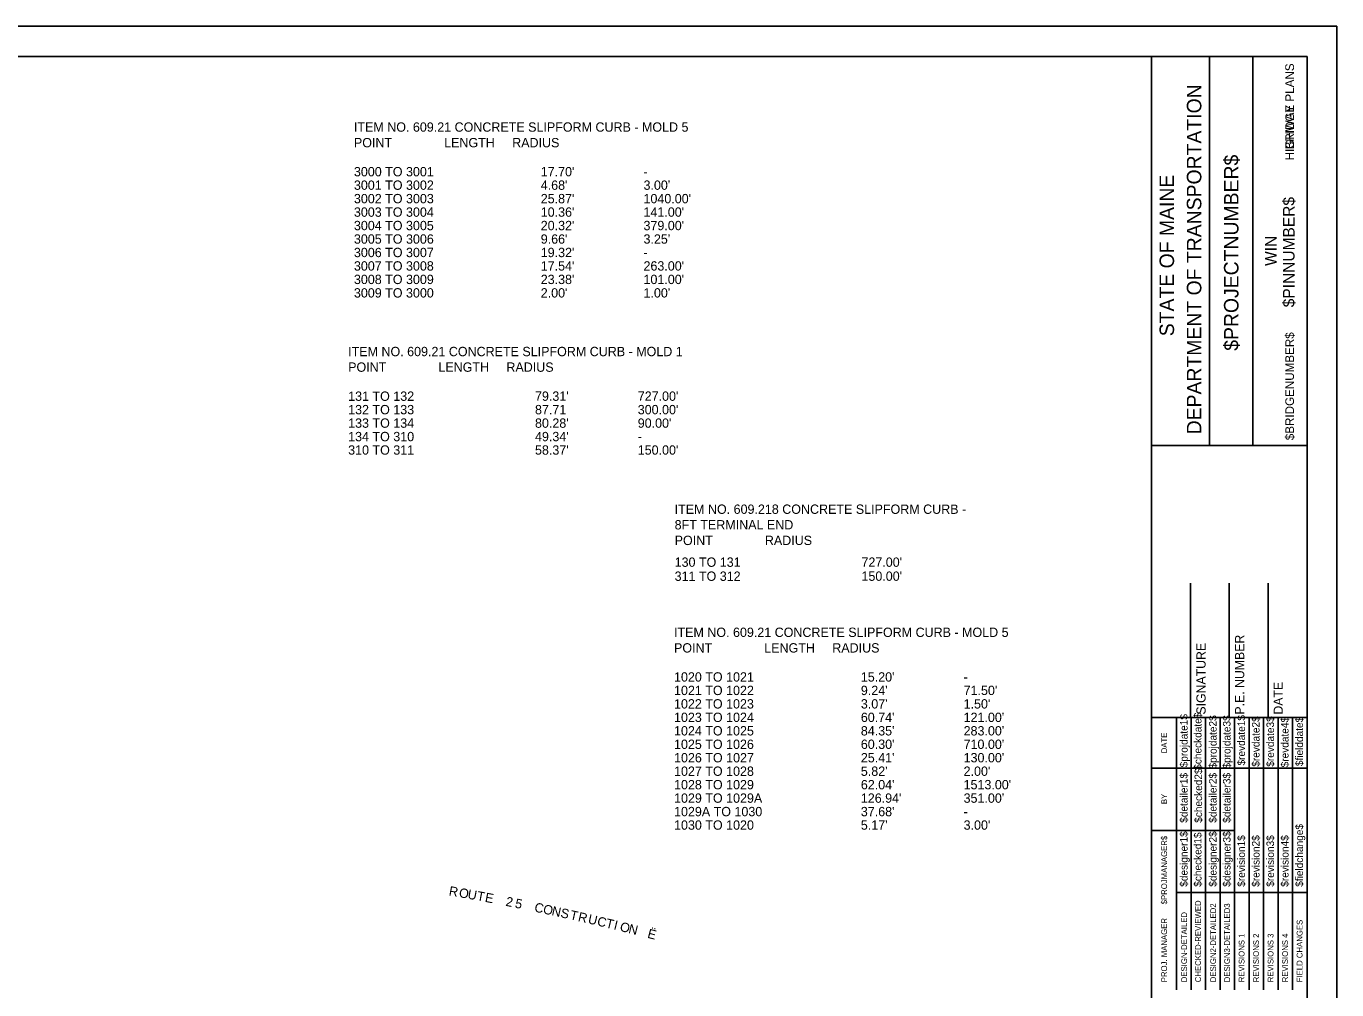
# Model space of a CAD drawing. Extents: x 916257 to 917115, y 329394 to 329944.
# Drawn here: x 916686.1 to 917107, y 329634.2 to 329943.9 of the extents above; entities that cross this region are included whole.
import ezdxf

# ---------------------------------------------------------------- set-up
doc = ezdxf.new("R2010")
doc.units = 0
for name, color, linetype in [('ANNOTATION', 7, 'Continuous'), ('D_Curb_Type1_Lt', 7, 'Continuous'), ('D_Curb_Type_5_Lt', 7, 'Continuous'), ('D_Curb_Type_5_Rt', 7, 'Continuous'), ('D_Roadway_Edge_Pavement', 7, 'Continuous')]:
    doc.layers.add(name, color=color, linetype=linetype)

msp = doc.modelspace()

# ---------------------------------------------------------------- linework, layer by layer
at = {"layer": 'D_Curb_Type1_Lt'}
msp.add_lwpolyline([(916257, 329393.91), (917107, 329393.91), (917107, 329943.91), (916257, 329943.91)], close=True, dxfattribs=at)
at = {"layer": 'D_Roadway_Edge_Pavement'}
for p, q in [((917097.47, 329934.21), (916297.47, 329934.21)), ((917047.47, 329409.22), (917047.47, 329934.22)), ((917066.11, 329809.19), (917066.11, 329934.19)), ((917080.08, 329809.19), (917080.08, 329934.19)), ((917097.47, 329409.22), (917097.47, 329934.22)), ((917047.47, 329809.18), (917097.47, 329809.18)), ((917059.97, 329721.72), (917059.97, 329764.96)), ((917072.47, 329721.72), (917072.47, 329764.96)), ((917084.97, 329721.72), (917084.97, 329764.96)), ((917047.47, 329721.72), (917097.47, 329721.72))]:
    msp.add_line(p, q, dxfattribs=at)
for points in [[(917055.54, 329705.47), (917055.54, 329721.72)], [(917060.2, 329634.24), (917060.2, 329721.72)], [(917064.86, 329721.72), (917064.86, 329634.24)], [(917069.52, 329634.24), (917069.52, 329721.72)], [(917074.18, 329634.24), (917074.18, 329721.72)], [(917078.84, 329634.24), (917078.84, 329721.72)], [(917083.5, 329634.24), (917083.5, 329721.72)], [(917088.15, 329634.24), (917088.15, 329721.72)], [(917092.81, 329634.24), (917092.81, 329721.72)], [(917055.54, 329634.24), (917055.54, 329718.19)], [(917047.47, 329705.47), (917097.47, 329705.47)], [(917047.47, 329685.47), (917055.54, 329685.47)], [(917055.54, 329685.47), (917074.17, 329685.47)], [(917055.54, 329665.47), (917097.47, 329665.47)]]:
    msp.add_lwpolyline(points, dxfattribs=at)

# ---------------------------------------------------------------- texts
at = {"layer": 'ANNOTATION'}
for s, rotation, p in [('ITEM NO. 609.21 CONCRETE SLIPFORM CURB - MOLD 5', 0.0011, (916791.35, 329910)), ('POINT               LENGTH     RADIUS', 0.0011, (916791.35, 329904.99)), ('3000 TO 3001', 0.0011, (916791.35, 329895.66)), ("17.70'", 0.0011, (916851.35, 329895.66)), ('3001 TO 3002', 0.0011, (916791.35, 329891.33)), ("4.68'", 0.0011, (916851.35, 329891.33)), ("3.00'", 0.0011, (916884.35, 329891.33)), ('-', 0.0011, (916884.35, 329895.66)), ('3002 TO 3003', 0.0011, (916791.35, 329887)), ("25.87'", 0.0011, (916851.35, 329887)), ("1040.00'", 0.0011, (916884.35, 329887)), ('3003 TO 3004', 0.0011, (916791.35, 329882.67)), ("10.36'", 0.0011, (916851.35, 329882.68)), ("141.00'", 0.0011, (916884.35, 329882.68)), ('3004 TO 3005', 0.0011, (916791.35, 329878.35)), ("20.32'", 0.0011, (916851.35, 329878.35)), ("379.00'", 0.0011, (916884.35, 329878.35)), ('3005 TO 3006', 0.0011, (916791.35, 329874.02)), ("9.66'", 0.0011, (916851.35, 329874.02)), ("3.25'", 0.0011, (916884.35, 329874.02)), ('3006 TO 3007', 0.0011, (916791.35, 329869.69)), ("19.32'", 0.0011, (916851.35, 329869.69)), ('-', 0.0011, (916884.35, 329869.7)), ('3007 TO 3008', 0.0011, (916791.35, 329865.37)), ("17.54'", 0.0011, (916851.35, 329865.37)), ("263.00'", 0.0011, (916884.35, 329865.37)), ('3008 TO 3009', 0.0011, (916791.35, 329861.04)), ("23.38'", 0.0011, (916851.35, 329861.04)), ("101.00'", 0.0011, (916884.35, 329861.04)), ('3009 TO 3000', 0.0011, (916791.35, 329856.71)), ("2.00'", 0.0011, (916851.35, 329856.71)), ("1.00'", 0.0011, (916884.35, 329856.71)), ('ITEM NO. 609.21 CONCRETE SLIPFORM CURB - MOLD 1', 0.0011, (916789.5, 329837.86)), ('POINT               LENGTH     RADIUS', 0.0011, (916789.5, 329832.85)), ('131 TO 132', 0.0011, (916789.5, 329823.51)), ("79.31'", 0.0011, (916849.5, 329823.52)), ("727.00'", 0.0011, (916882.5, 329823.52)), ('132 TO 133', 0.0011, (916789.5, 329819.19)), ('87.71', 0.0011, (916849.5, 329819.19)), ("300.00'", 0.0011, (916882.5, 329819.19)), ('133 TO 134', 0.0011, (916789.5, 329814.86)), ("80.28'", 0.0011, (916849.5, 329814.86)), ("90.00'", 0.0011, (916882.5, 329814.86)), ('134 TO 310', 0.0011, (916789.5, 329810.53)), ("49.34'", 0.0011, (916849.5, 329810.53)), ('-', 0.0011, (916882.5, 329810.54)), ('310 TO 311', 0.0011, (916789.5, 329806.21)), ("58.37'", 0.0011, (916849.5, 329806.21)), ("150.00'", 0.0011, (916882.5, 329806.21)), ('ITEM NO. 609.218 CONCRETE SLIPFORM CURB -', 0.0011, (916894.35, 329787.19)), ('8FT TERMINAL END', 0.0011, (916894.35, 329782.18)), ('POINT               RADIUS', 0.0011, (916894.35, 329777.17)), ('130 TO 131', 0.0011, (916894.35, 329770.17)), ("727.00'", 0.0011, (916954.35, 329770.17)), ('311 TO 312', 0.0011, (916894.35, 329765.66)), ("150.00'", 0.0011, (916954.35, 329765.67)), ('ITEM NO. 609.21 CONCRETE SLIPFORM CURB - MOLD 5', 0.0011, (916894.15, 329747.63)), ('POINT               LENGTH     RADIUS', 0.0011, (916894.15, 329742.62)), ('1020 TO 1021', 0.0011, (916894.15, 329733.28)), ("15.20'", 0.0011, (916954.15, 329733.28)), ('-', 0.0011, (916987.15, 329733.28)), ('1021 TO 1022', 0.0011, (916894.15, 329728.95)), ("9.24'", 0.0011, (916954.15, 329728.95)), ("71.50'", 0.0011, (916987.15, 329728.96)), ('1022 TO 1023', 0.0011, (916894.15, 329724.63)), ("3.07'", 0.0011, (916954.15, 329724.63)), ("1.50'", 0.0011, (916987.15, 329724.63)), ('1023 TO 1024', 0.0011, (916894.15, 329720.3)), ("60.74'", 0.0011, (916954.15, 329720.3)), ("121.00'", 0.0011, (916987.15, 329720.3)), ('1024 TO 1025', 0.0011, (916894.15, 329715.97)), ("84.35'", 0.0011, (916954.15, 329715.97)), ("283.00'", 0.0011, (916987.15, 329715.97)), ('1025 TO 1026', 0.0011, (916894.15, 329711.64)), ("60.30'", 0.0011, (916954.15, 329711.65)), ("710.00'", 0.0011, (916987.15, 329711.65)), ('1026 TO 1027', 0.0011, (916894.16, 329707.32)), ("25.41'", 0.0011, (916954.15, 329707.32)), ("130.00'", 0.0011, (916987.15, 329707.32)), ('1027 TO 1028', 0.0011, (916894.16, 329702.99)), ("5.82'", 0.0011, (916954.15, 329702.99)), ("2.00'", 0.0011, (916987.15, 329702.99)), ('1028 TO 1029', 0.0011, (916894.16, 329698.66)), ("62.04'", 0.0011, (916954.15, 329698.66)), ("1513.00'", 0.0011, (916987.15, 329698.67)), ('1029 TO 1029A', 0.0011, (916894.16, 329694.34)), ("126.94'", 0.0011, (916954.15, 329694.34)), ("351.00'", 0.0011, (916987.15, 329694.34)), ('1029A TO 1030', 0.0011, (916894.16, 329690.01)), ("37.68'", 0.0011, (916954.15, 329690.01)), ('1030 TO 1020', 0.0011, (916894.16, 329685.68)), ("5.17'", 0.0011, (916954.15, 329685.68)), ("3.00'", 0.0011, (916987.15, 329685.68)), ('-', 0.0011, (916987.15, 329690.01)), ('R', 350.0375, (916821.69, 329664.62)), ('O', 349.8139, (916824.91, 329664.06)), ('U', 349.6197, (916827.7, 329663.56)), ('T', 349.4146, (916830.65, 329663.02)), ('E', 349.2318, (916833.27, 329662.53)), ('2', 348.7682, (916839.92, 329661.25)), ('5', 348.5594, (916842.91, 329660.66)), ('C', 348.1251, (916849.13, 329659.39)), ('O', 347.9309, (916851.91, 329658.8)), ('N', 347.7367, (916854.68, 329658.21)), ('S', 347.5386, (916857.51, 329657.6)), ('T', 347.3261, (916860.54, 329656.93)), ('R', 347.1434, (916863.14, 329656.34)), ('U', 346.9199, (916866.33, 329655.62)), ('C', 346.7147, (916869.25, 329654.94)), ('T', 346.5205, (916872.01, 329654.29)), ('I', 346.3378, (916874.6, 329653.67)), ('O', 346.1997, (916876.56, 329653.19)), ('N', 346.0055, (916879.32, 329652.52)), ('Ë', 345.5747, (916885.42, 329650.98))]:
    msp.add_text(s, height=3, rotation=rotation, dxfattribs=at).set_placement(p)
at = {"layer": 'D_Curb_Type_5_Lt'}
msp.add_text('HIGHWAY PLANS', height=2.795, rotation=90, dxfattribs=at).set_placement((917093.26, 329900.79))
at = {"layer": 'D_Curb_Type_5_Rt'}
for s, p in [('BRIDGE PLANS', (917093.26, 329904.33)), ('$BRIDGENUMBER$', (917093.26, 329810.86))]:
    msp.add_text(s, height=2.795, rotation=90, dxfattribs=at).set_placement(p)
at = {"layer": 'D_Roadway_Edge_Pavement'}
for s, height, p in [('DEPARTMENT OF TRANSPORTATION', 4.6588, (917063.5, 329812.74)), ('$PROJECTNUMBER$', 4.6588, (917075.43, 329839.6)), ('STATE OF MAINE', 4.6588, (917054.74, 329844.27)), ('$PINNUMBER$', 3.7264, (917093.44, 329853.58)), ('WIN', 3.726, (917087.65, 329866.86)), ('P.E. NUMBER', 2.9528, (917077.27, 329722.68)), ('SIGNATURE', 2.953, (917064.87, 329722.68)), ('DATE', 2.953, (917089.67, 329722.68)), ('$projdate1$', 2.4227, (917059.08, 329705.73)), ('$checkdate$', 2.4227, (917063.55, 329704.94)), ('$projdate2$', 2.4227, (917068.4, 329705.33)), ('$projdate3$', 2.4227, (917072.87, 329705.33)), ('$revdate1$', 2.423, (917077.53, 329706.32)), ('$revdate2$', 2.423, (917082.19, 329705.92)), ('$revdate3$', 2.423, (917086.84, 329705.92)), ('$revdate4$', 2.423, (917091.5, 329705.73)), ('$fielddate$', 2.4227, (917096.16, 329706.12)), ('DATE', 1.857, (917052.49, 329710.25)), ('$checked2$', 2.423, (917063.74, 329687.9)), ('$detailer1$', 2.4227, (917059.08, 329687.9)), ('$detailer2$', 2.4227, (917068.4, 329687.9)), ('$detailer3$', 2.4227, (917072.87, 329687.9)), ('BY', 1.857, (917052.49, 329693.9)), ('$PROJMANAGER$', 1.8637, (917052.49, 329661.7)), ('$designer1$', 2.4227, (917059.08, 329667.34)), ('$checked1$', 2.423, (917063.55, 329667.34)), ('$designer2$', 2.4227, (917068.4, 329667.34)), ('$designer3$', 2.4227, (917072.87, 329667.34)), ('$revision1$', 2.4227, (917077.53, 329667.34)), ('$revision2$', 2.4227, (917082.19, 329667.34)), ('$revision3$', 2.4227, (917086.84, 329667.34)), ('$revision4$', 2.4227, (917091.5, 329667.34)), ('$fieldchange$', 2.4227, (917096.16, 329667.34)), ('CHECKED-REVIEWED', 1.8637, (917063.37, 329636.66)), ('DESIGN-DETAILED', 1.8637, (917058.9, 329636.66)), ('DESIGN2-DETAILED2', 1.8637, (917068.22, 329636.66)), ('DESIGN3-DETAILED3', 1.8637, (917072.69, 329636.66)), ('PROJ. MANAGER', 1.8637, (917052.49, 329636.66)), ('FIELD CHANGES', 1.8637, (917095.98, 329636.66)), ('REVISIONS 1', 1.8637, (917077.35, 329636.66)), ('REVISIONS 2', 1.8637, (917082, 329636.66)), ('REVISIONS 3', 1.8637, (917086.66, 329636.66)), ('REVISIONS 4', 1.8637, (917091.32, 329636.66))]:
    msp.add_text(s, height=height, rotation=90, dxfattribs=at).set_placement(p)

doc.saveas('drawing.dxf')
